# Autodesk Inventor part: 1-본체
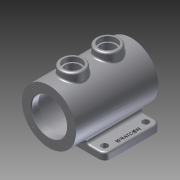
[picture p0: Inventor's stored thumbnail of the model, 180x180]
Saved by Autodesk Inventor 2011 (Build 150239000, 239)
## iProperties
Created: 2014-12
Part Number: 1-본체
Document SubType Name: Modeling
Designer: user
Density: 1 g/cm^3
Mass: 480.321 g
Surface Area: 1048.07 cm^2
Volume: 480.321 cm^3
Author: user
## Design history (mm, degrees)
sketch "스케치1"
  geometry: L1 (-47.5, 65)-(47.5, 65); L2 (47.5, 65)-(47.5, -65); L3 (47.5, -65)-(-47.5, -65); L4 (-47.5, -65)-(-47.5, 65); 3 further points
  constraints: 8 end point, 2 midpoint, 2 parallel, 1 horizontal, 1 horizontal alignment, 1 perpendicular, 1 vertical alignment
  dimensions: "d0" = 130 distance of L1.end L2.end; "d1" = 95 distance of L1.start L1.end
extrude "돌출1" new body sketch "스케치1" distance "d2" = 12; taper "d3" = 0 deg
sketch "스케치2"
  geometry: L1 (47.5, 12)-(47.5, 0) reference; L2 (47.5, 0)-(-47.5, 0) reference; L3 (-47.5, 0)-(-47.5, 12) reference; L4 (-47.5, 12)-(47.5, 12) reference; L5 (-77.5, 96)-(62.5, 96); L6 (62.5, 96)-(62.5, 50); L7 (-77.5, 50)-(-77.5, 96); L8 (-77.5, 50)-(62.5, 50); L9 (-77.5, 80)-(-65.5, 80); L10 (-65.5, 80)-(-65.5, 87.5); L11 (-65.5, 87.5)-(50.5, 87.5); L12 (50.5, 87.5)-(50.5, 80); L13 (50.5, 80)-(62.5, 80); 1 further point
  constraints: 18 end point, 5 parallel, 4 perpendicular, 2 point on line
  dimensions: "d5" = 50 distance from line of L2 L6.end; "d6" = 15 distance between parallel lines of L1 L6; "d7" = 30 distance between parallel lines of L3 L7; "d8" = 12 distance of L9.start L9.end; "d9" = 12 distance of L12.end L13.end; "d10" = 60 diameter of L9 L8; "d11" = 60 diameter of L13 L8; "d12" = 75 diameter of L11 L8; "d14" = 92 diameter of L5 L8
revolve "회전1" sketch "스케치2" stored, may be unused: angle "d15" = 90 deg
node "작업 평면1"
sketch "스케치3"
  geometry: L1 (77.5, 46)-(77.5, -46) reference; L2 (-62.5, 46)-(-62.5, -46) reference; C1 r 20 at (37.5, 0); C2 r 20 at (-22.5, 0); 1 further point
  constraints: 2 centre point
  dimensions: "d17" = 40 diameter of C1; "d18" = 40 diameter of C2; "d19" = 40 distance from line of L1 C1.centre; "d20" = 40 distance from line of L2 C2.centre
extrude "돌출2" join sketch "스케치3" stored distance "d21" = 10; taper "d22" = 0 deg
hole "Hole1" diameter "d25" = 25; stored, may be unused: countersink angle "d29" = 90 deg, drill point angle "d31" = 0 deg; dims "d23" = 10, "d24" = 10, "d26" = 6, "d27" = 30, "d28" = 8, "d30" = 8
hole "Hole2" diameter "d34" = 25; stored, may be unused: countersink angle "d38" = 90 deg, drill point angle "d40" = 0 deg; dims "d32" = 10, "d33" = 10, "d35" = 6, "d36" = 30, "d37" = 8, "d39" = 8
fillet "모깎기1" dims "d41" = 10
fillet "모깎기4" dims "d44" = 3
fillet "모깎기5" dims "d45" = 3
fillet "모깎기6" dims "d46" = 3
chamfer "모따기1" distance "d47" = 1; stored, may be unused: second distance "d48" = 2, angle "d49" = 45 deg
sketch "스케치4"
  geometry: L1 (77.5, 25.923)-(77.5, -25.923) reference; L2 (-62.5, -25.923)-(-62.5, 25.923) reference; L3 (-62.5, 25.923)-(-47.5, 25.923) reference; L4 (47.5, 25.923)-(77.5, 25.923) reference; L5 (77.5, -25.923)-(47.5, -25.923) reference; L6 (-47.5, -25.923)-(-62.5, -25.923) reference; L7 (47.5, 55)-(47.5, 25.923) reference; L8 (47.5, -25.923)-(-47.5, -25.923) reference; L9 (-47.5, 25.923)-(-47.5, 55) reference; L10 (-37.5, 65)-(37.5, 65) reference; L11 (-47.5, 25.923)-(47.5, 25.923) reference; L12 (47.5, -25.923)-(47.5, -55) reference; L13 (37.5, -65)-(-37.5, -65) reference; L14 (-47.5, -55)-(-47.5, -25.923) reference; L15 (37.5, -65)-(-37.5, -65) reference; L16 (0, -65)-(0, 65); L17 (-62.5, 0)-(77.5, 0); L18 (-35, -52)-(35, -52); L19 (-35, 52)-(-35, -52); L20 (-35, 52)-(35, 52); L21 (35, -52)-(35, 52); A1 r 10 centre (37.5, 55) between (47.5, 55) and (37.5, 65) reference; A2 r 10 centre (-37.5, 55) between (-37.5, 65) and (-47.5, 55) reference; A3 r 10 centre (37.5, -55) between (37.5, -65) and (47.5, -55) reference; A4 r 10 centre (-37.5, -55) between (-47.5, -55) and (-37.5, -65) reference; 3 further points
  constraints: 12 end point, 4 midpoint, 3 perpendicular, 1 coincident, 1 parallel
  dimensions: "d73" = 104 distance of L19.start L18.start; "d74" = 70 distance of point (35, 52) L19.start; "d75" = 104 distance of point (35, -52) point (35, 52); "d76" = 70 distance of L18.start point (35, -52); "d77" = 35 distance from line of L16 L19.start; "d78" = 52 distance between parallel lines of L20 L17
hole "Hole3" sketch "스케치4" at (-35, -52), (35, -52), (35, 52), (-35, 52) diameter "d50" = 11; stored, may be unused: countersink angle "d54" = 90 deg, drill point angle "d56" = 118 deg; dims "d51" = 6, "d52" = 30, "d53" = 8, "d55" = 8
sketch "스케치5" dims "d58" = 80
  geometry: L1 (0, 0)-(50, 50); L2 (0, 0)-(70.711, 0); C1 r 31 at (0, 0) reference; 3 further points
  constraints: 4 end point, 1 coincident, 1 equal length, 1 horizontal, 1 point on line, 3 other
  dimensions: "d57" = 45 deg angle of L2 L1
hole "Hole4" sketch "스케치5" at (28.284, 28.284) diameter "d59" = 3.242; stored, may be unused: countersink angle "d63" = 90 deg, drill point angle "d65" = 118 deg; dims "d60" = 8, "d61" = 30, "d62" = 8, "d64" = 10
node "작업 평면2"
fillet "모깎기10" dims "d79" = 3
fillet "모깎기11" dims "d80" = 5
fillet "모깎기12" dims "d81" = 3
sketch "스케치6"
  geometry: L1 (14.878, 57.409)-(-14.878, 57.409); L2 (-14.878, 57.409)-(-14.878, 56.591); L3 (-14.878, 56.591)-(14.878, 56.591); L4 (14.878, 56.591)-(14.878, 57.409); L5 (37.5, 65)-(-37.5, 65) reference; C1 r 5.5 at (35, 52) reference; 3 further points
  constraints: 2 midpoint, 2 other
  dimensions: "d82" = 35 horizontal distance of point (0, 56.591) C1.centre; "d83" = 8 distance from line of L5 point (14.878, 57)
feature "엠보싱1" sketch "스케치6" dims "d0" = 130, "d1" = 95, "d16" = 108, "d84" = 1, "d85" = 0
node "솔리드1"
pattern_circular "원형 패턴1" dims angle "d67" = 360 deg
mirror "대칭1"
node "절단 모서리 투영1"
node "절단 모서리 투영2"
